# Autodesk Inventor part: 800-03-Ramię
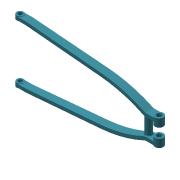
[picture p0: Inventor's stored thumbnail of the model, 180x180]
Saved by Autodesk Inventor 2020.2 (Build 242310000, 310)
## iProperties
Created: 2014-12
Part Number: 800-03-Ramię
Material: Aluminium 6061
Document SubType Name: Modeling
Designer: F.Stasiak
Density: 2.7 g/cm^3
Appearance: Niebieska z odcieniem szarości
Mass: 74.2736 g
Surface Area: 436.313 cm^2
Volume: 74.2736 cm^3
Catalog Web Link: www.expertbooks.pl
Manager: www.cadconsulting.pl
Company: Fabian Stasiak CAD Consulting
Author: F.Stasiak
Subject: Zbiór ćwiczeń. Autodesk Inventor 2020. Kurs Professional
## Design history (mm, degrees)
node "Płaszczyzna konstrukcyjna1"
sketch "Szkic2"
  geometry: L1 (79.08, -14.077)-(79.08, 20.923); L2 (49.783, 126.447)-(34.08, 305.923); L3 (34.08, 305.923)-(34.08, 335.923); L4 (26.08, 335.923)-(26.08, 305.574); L5 (26.08, 305.574)-(41.813, 125.749); L6 (71.08, 19.086)-(71.08, -14.077); L7 (34.08, 335.923)-(26.08, 335.923); L8 (79.08, -14.077)-(71.08, -14.077); A1 r 300 centre (348.641, 152.593) between (49.783, 126.447) and (79.08, 20.923); A2 r 308 centre (348.641, 152.593) between (41.813, 125.749) and (71.08, 19.086); 1 further point
  constraints: 16 end point, 4 point on circle, 2 centre point, 2 vertical, 1 coincident, 1 horizontal, 1 parallel, 1 tangent, 3 other
  dimensions: "d0" = 35 distance of L1.start L1.end; "d3" = 300 radius of A1; "d4" = 5 deg angle of L1 L2; "d6" = 30 distance of L2.end L3.end; "d7" = 350 vertical distance of L3.end point (79.08, -14.077); "d8" = 45 horizontal distance of L1.end L3.end; "d9" = 8 distance between parallel lines of L2 L5
extrude "Wyciągnięcie proste1" new body sketch "Szkic2" stored distance "d10" = 20; taper "d11" = 0 deg
feature "Pochylenie ściany1" dims angle "d12" = -0.3 deg
fillet "Zaokrąglenie1"
fillet "Zaokrąglenie2" dims "d13" = 10
fillet "Zaokrąglenie4" dims "d15" = 15
fillet "Zaokrąglenie5" dims "d16" = 23
sketch "Szkic3"
  geometry: C1 r 10 at (19.786, 9.792); A1 r 10 centre (19.786, 9.792) between (29.786, 9.792) and (19.734, 19.791) reference; 1 further point
  constraints: 1 centre point, 1 coincident
  dimensions: "d18" = 20 diameter of C1
extrude "Wyciągnięcie proste2" join sketch "Szkic3" distance "d19" = 2; taper "d21" = 0 deg; dims "d20" = 17, "d22" = 0
sketch "Szkic5"
  geometry: C1 r 10 at (0, 0) reference; C2 r 6 at (0, 0); 1 further point
  constraints: 1 centre point, 1 coincident
  dimensions: "d30" = 12 diameter of C2
extrude "Wyciągnięcie proste4" cut sketch "Szkic5" extent not by distance; stored distance "d31" = 5; taper "d32" = 0 deg
sketch "Szkic8"
  geometry: A1 r 8.21 centre (-22.139, 8.326) between (-22.182, 16.536) and (-22.182, 0.116) reference; 2 further points
  constraints: 1 coincident, 3 other
extrude "Wyciągnięcie proste7" join sketch "Szkic8" distance "d48" = 1; taper "d50" = 0 deg; dims "d49" = 9, "d51" = 0
sketch "Szkic9"
  geometry: C1 r 8.21 at (0, 0) reference; C2 r 5 at (0, 0); 1 further point
  constraints: 1 centre point, 1 coincident
  dimensions: "d52" = 10 diameter of C2
extrude "Wyciągnięcie proste8" cut sketch "Szkic9" extent not by distance; stored distance "d53" = 1; taper "d54" = 0 deg
node "Płaszczyzna konstrukcyjna3"
sketch "Szkic11"
  geometry: C1 r 7.5 at (25, 0); C2 r 6 at (0, 0) reference; 1 further point
  constraints: 1 centre point, 1 horizontal alignment
  dimensions: "d60" = 15 diameter of C1; "d61" = 25 distance of C2.centre C1.centre
extrude "Wyciągnięcie proste10" join sketch "Szkic11" stored distance "d62" = 10; taper "d63" = 0 deg
fillet "Zaokrąglenie13" dims "d64" = 2
mirror "Odbicie lustrzane1"
node "Bryła1"
other parameters: "d55" = 11.5
